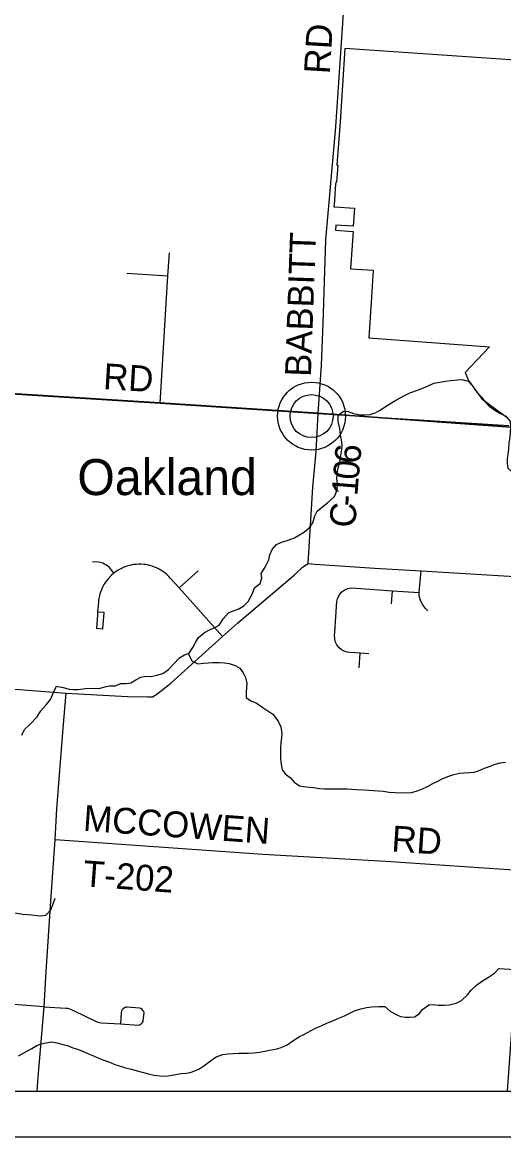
# Model space of a CAD drawing. Extents: x 0 to 91.3, y -0.7 to 22.
# Drawn here: x 3.464 to 4.519, y 14 to 16.443 of the extents above; entities that cross this region are included whole.
import ezdxf

# ---------------------------------------------------------------- set-up
doc = ezdxf.new("R2010")
doc.units = 0
for name, color, linetype in [('GM_X_Corporation', 7, 'Continuous'), ('GM_X_County_Road', 7, 'Continuous'), ('GM_X_County_Road_Text', 7, 'Continuous'), ('GM_X_Minor_River', 7, 'Continuous'), ('GM_X_Township_Road', 7, 'Continuous'), ('GM_X_Township_Road_Text', 7, 'Continuous'), ('GM_X_Unincorporated', 7, 'Continuous'), ('GM_X_Unincorporated_Location', 7, 'Continuous'), ('GM_X_Unincorporated_Text', 7, 'Continuous'), ('SH_Data', 7, 'Continuous')]:
    doc.layers.add(name, color=color, linetype=linetype)

msp = doc.modelspace()

# ---------------------------------------------------------------- linework, layer by layer
at = {"layer": 'GM_X_Corporation'}
for points in [[(2.1, 20.8844), (2.1, 14.1), (4.5273, 14.1), (4.5361, 14.2234), (4.5616, 14.5843), (4.5901, 15.0403), (4.6027, 15.2253), (4.6241, 15.5494), (4.624, 15.5538), (4.6966, 16.7952), (4.7039, 16.921), (4.7369, 17.4842), (4.7381, 17.5094), (4.7391, 17.5254), (4.7562, 17.8002), (4.7688, 17.9561), (4.7799, 18.0944), (4.7833, 18.1361), (4.8242, 18.6326)], [(2.1, 20.8844), (2.1, 15.7138), (2.3611, 15.6969), (2.7426, 15.6727), (3.1007, 15.6507), (3.7652, 15.6088), (4.1118, 15.5861), (4.6241, 15.5494), (4.624, 15.5538), (4.6966, 16.7952), (4.7039, 16.921), (4.7369, 17.4842), (4.7381, 17.5094), (4.7391, 17.5254), (4.7562, 17.8002), (4.7688, 17.9561), (4.7799, 18.0944), (4.7833, 18.1361), (4.8242, 18.6326)], [(4.5546, 16.3598), (4.1706, 16.3862), (4.16, 16.225), (4.1532, 16.1304), (4.1551, 16.1302), (4.1524, 16.0927), (4.1505, 16.0926), (4.1496, 16.0795), (4.1486, 16.0657), (4.1476, 16.0522), (4.1467, 16.0387), (4.1482, 16.0387), (4.1915, 16.036), (4.19, 16.0161), (4.1884, 15.9961), (4.1509, 15.9985), (4.1502, 15.9873), (4.189, 15.9846), (4.1876, 15.9653), (4.1831, 15.903), (4.2328, 15.8999), (4.2283, 15.8297), (4.2234, 15.7519), (4.4873, 15.7321), (4.434, 15.6753), (4.4414, 15.6583), (4.4708, 15.6178), (4.5262, 15.577)]]:
    msp.add_lwpolyline(points, dxfattribs=at)
msp.add_lwpolyline([(2.1, 15.7138), (2.1, 14.1), (4.5273, 14.1), (4.5361, 14.2234), (4.5616, 14.5843), (4.5901, 15.0403), (4.6027, 15.2253), (4.6241, 15.5494), (4.1118, 15.5861), (3.7652, 15.6088), (3.1007, 15.6507), (2.7426, 15.6727), (2.3611, 15.6969)], close=True, dxfattribs=at)
at = {"layer": 'GM_X_County_Road'}
msp.add_line((4.112, 15.5855), (4.5298, 15.5592), dxfattribs=at)
for points in [[(4.112, 15.5855), (4.1196, 15.6918), (4.1232, 15.7838), (4.1286, 15.9666), (4.1509, 16.2143), (4.1988, 16.9297), (4.2129, 17.1593), (4.2202, 17.2471)], [(2.7944, 15.669), (3.1009, 15.6502), (3.7654, 15.6083), (4.112, 15.5855)], [(4.0898, 15.2565), (4.1003, 15.4241), (4.1076, 15.5024), (4.112, 15.5855)], [(3.9024, 15.0967), (3.9353, 15.1263), (4.0599, 15.2323), (4.0777, 15.2484), (4.0898, 15.2565)], [(4.0898, 15.2565), (4.1044, 15.2553), (4.2363, 15.2464), (4.3377, 15.2405), (4.603, 15.2248)], [(3.5594, 14.9727), (3.6939, 14.9655), (3.7377, 14.9648), (3.7487, 14.9646), (3.7581, 14.97), (3.7893, 14.9946), (3.9024, 15.0967)], [(2.5387, 15.0425), (2.6121, 15.0373), (2.706, 15.0307), (2.8364, 15.0213), (2.8571, 15.0199), (2.971, 15.012), (3.0369, 15.0072), (3.0952, 15.0032), (3.3423, 14.9878), (3.4576, 14.9802), (3.5594, 14.9727)], [(3.4961, 14.1), (3.4984, 14.1303), (3.5113, 14.2849), (3.5159, 14.3624), (3.5261, 14.5167), (3.5357, 14.6514), (3.5391, 14.7192), (3.553, 14.8961), (3.5594, 14.9727)]]:
    msp.add_lwpolyline(points, dxfattribs=at)
at = {"layer": 'GM_X_Minor_River'}
for points in [[(3.5761, 14.9807), (3.586, 14.9806), (3.6019, 14.9824), (3.6179, 14.9834), (3.6319, 14.983), (3.6441, 14.9863), (3.6547, 14.9885), (3.6676, 14.9888), (3.679, 14.9937), (3.6912, 14.9936), (3.7014, 14.9955), (3.7121, 15.0019), (3.7235, 15.0079), (3.7353, 15.0097), (3.7459, 15.0092), (3.7585, 15.0122), (3.7718, 15.0159), (3.784, 15.0246), (3.795, 15.0363), (3.8084, 15.0499), (3.8191, 15.0562), (3.8294, 15.0604), (3.8374, 15.0728), (3.8428, 15.0834), (3.8501, 15.0944), (3.863, 15.1057), (3.8756, 15.1121), (3.8855, 15.1162), (3.895, 15.1218), (3.9046, 15.1362), (3.9157, 15.1487), (3.9282, 15.1535), (3.9385, 15.1572), (3.9488, 15.164), (3.9587, 15.1738), (3.9672, 15.1897), (3.9726, 15.2033), (3.9848, 15.2128), (3.9883, 15.2256), (3.9868, 15.2351), (3.9956, 15.2491), (4.0037, 15.265), (4.0064, 15.2756), (4.0114, 15.2874), (4.021, 15.2987), (4.0316, 15.3036), (4.0442, 15.3073), (4.0602, 15.3133), (4.0708, 15.3197), (4.0819, 15.326), (4.093, 15.3358), (4.1006, 15.346), (4.1045, 15.3612), (4.1099, 15.3718), (4.1232, 15.3827), (4.1328, 15.3899), (4.1476, 15.4038), (4.1534, 15.4182), (4.1543, 15.4323), (4.1528, 15.4421), (4.154, 15.4516), (4.1552, 15.4634), (4.1599, 15.4831), (4.1619, 15.4933), (4.1639, 15.5066), (4.1643, 15.5172), (4.1632, 15.5279), (4.161, 15.5385), (4.1592, 15.5529), (4.1559, 15.5681), (4.156, 15.5822), (4.1678, 15.5908), (4.178, 15.59), (4.1898, 15.5858), (4.2038, 15.583), (4.2152, 15.5826), (4.2262, 15.5836), (4.2368, 15.5874), (4.2467, 15.5923), (4.2631, 15.6035), (4.2799, 15.6137), (4.2917, 15.6201), (4.3012, 15.6253), (4.3115, 15.6302), (4.3256, 15.6351), (4.3358, 15.6392), (4.3514, 15.6455), (4.3659, 15.6519), (4.3784, 15.6545), (4.3914, 15.6563), (4.4035, 15.6577), (4.4172, 15.6592), (4.4267, 15.6603), (4.4407, 15.6564), (4.4494, 15.6468), (4.4584, 15.635), (4.4697, 15.6213), (4.478, 15.6114), (4.4867, 15.6018), (4.4991, 15.593), (4.5101, 15.5865)], [(4.5101, 15.5865), (4.5233, 15.5796), (4.5328, 15.5678), (4.5338, 15.5564), (4.5326, 15.5431), (4.5318, 15.5336), (4.5302, 15.5211), (4.529, 15.5078), (4.5274, 15.4965), (4.5266, 15.4866), (4.5265, 15.4767), (4.5276, 15.4661), (4.54, 15.455), (4.5517, 15.4462), (4.5638, 15.437), (4.5778, 15.4278), (4.6085, 15.4127)], [(3.8273, 15.0595), (3.8357, 15.0429), (3.8486, 15.0371), (3.8607, 15.0382), (3.871, 15.0392), (3.8808, 15.0396), (3.8941, 15.0395), (3.907, 15.039), (3.9173, 15.0378), (3.9298, 15.0328), (3.94, 15.0274), (3.9479, 15.0168), (3.9524, 15.0069), (3.9557, 14.9947), (3.9553, 14.9848), (3.9544, 14.975), (3.9544, 14.9632), (3.9642, 14.956), (3.9763, 14.9513), (3.9884, 14.9425), (3.9997, 14.9352), (4.0126, 14.9268), (4.0246, 14.9112), (4.0303, 14.8986), (4.0321, 14.8846), (4.0316, 14.8743), (4.03, 14.8645), (4.0296, 14.8527), (4.0294, 14.8299), (4.0309, 14.8163), (4.0331, 14.8053), (4.0399, 14.7957), (4.0512, 14.7866), (4.0591, 14.777), (4.0712, 14.769), (4.0807, 14.7682), (4.0924, 14.7666), (4.1019, 14.7654), (4.1148, 14.7634), (4.1258, 14.7626), (4.1383, 14.7625), (4.1501, 14.7628), (4.1759, 14.7627), (4.1861, 14.7618), (4.196, 14.7614), (4.2116, 14.7602), (4.2233, 14.7597), (4.2336, 14.7589), (4.2446, 14.7585), (4.2548, 14.7576), (4.2677, 14.7557), (4.281, 14.7544), (4.306, 14.7543), (4.3163, 14.755), (4.3269, 14.7576), (4.3395, 14.7617), (4.3517, 14.7681), (4.3631, 14.7741), (4.3741, 14.7797), (4.3855, 14.7853), (4.3985, 14.7902), (4.4095, 14.7939), (4.4217, 14.7969), (4.4312, 14.798), (4.4441, 14.7986), (4.4536, 14.7993), (4.4635, 14.8023), (4.4768, 14.8079), (4.4878, 14.812), (4.4977, 14.8158), (4.511, 14.8195), (4.5224, 14.8213)], [(3.4624, 14.8804), (3.4681, 14.8925), (3.4811, 14.9046), (3.4964, 14.9204), (3.5044, 14.9336), (3.5159, 14.9469), (3.5255, 14.9589), (3.532, 14.9741), (3.5382, 14.9881), (3.553, 14.9846), (3.5666, 14.9811), (3.5761, 14.9807)], [(3.447, 14.4907), (3.4645, 14.488), (3.474, 14.4871), (3.4846, 14.4863), (3.4956, 14.4851), (3.5058, 14.4843), (3.5153, 14.4854), (3.526, 14.4975), (3.531, 14.5103), (3.5353, 14.5228)], [(3.8339, 14.1412), (3.8502, 14.1479), (3.8613, 14.1551), (3.8762, 14.1667), (3.8887, 14.1754), (3.9028, 14.1802), (3.9138, 14.1817), (3.926, 14.1824), (3.9385, 14.1831), (3.948, 14.183), (3.9586, 14.1833), (3.9719, 14.184), (3.9833, 14.1851), (3.9951, 14.1873), (4.0057, 14.1895), (4.0213, 14.1928), (4.0312, 14.1954), (4.0441, 14.2014), (4.0567, 14.2101), (4.0712, 14.2198), (4.0807, 14.2243), (4.0967, 14.233), (4.1074, 14.2386), (4.1184, 14.2431), (4.1325, 14.2495), (4.1443, 14.2543), (4.1549, 14.2592), (4.1694, 14.2652), (4.1812, 14.2712), (4.1915, 14.2761), (4.2059, 14.2805), (4.2181, 14.2835), (4.2299, 14.2846), (4.2443, 14.2856), (4.2579, 14.2852), (4.2708, 14.2748), (4.2829, 14.2679), (4.2927, 14.2637), (4.3037, 14.2621), (4.3136, 14.2621), (4.3235, 14.2628), (4.3337, 14.2691), (4.341, 14.279), (4.3547, 14.2891), (4.365, 14.2898), (4.376, 14.2886), (4.3893, 14.2882), (4.3991, 14.2889), (4.4147, 14.2926), (4.4265, 14.2986), (4.4391, 14.311), (4.4472, 14.3212), (4.459, 14.3322), (4.4701, 14.3401), (4.4857, 14.3495), (4.4986, 14.3585), (4.5082, 14.3691), (4.5434, 14.3663)], [(3.4549, 14.1772), (3.4645, 14.1825), (3.4751, 14.1885), (3.4846, 14.1937), (3.4953, 14.1997), (3.5048, 14.2035), (3.5151, 14.2057), (3.528, 14.2079), (3.5432, 14.2051), (3.5526, 14.2024), (3.5625, 14.1997), (3.5746, 14.1951), (3.5845, 14.192), (3.5977, 14.1866), (3.6087, 14.182), (3.6193, 14.177), (3.6291, 14.1728), (3.642, 14.1681), (3.6534, 14.1639), (3.6666, 14.1581), (3.6764, 14.1554), (3.6897, 14.1511), (3.7026, 14.148), (3.7155, 14.1442), (3.7261, 14.1418), (3.7405, 14.1379), (3.7518, 14.1348), (3.7659, 14.1332), (3.7765, 14.1328), (3.7879, 14.1342), (3.8004, 14.1364), (3.8111, 14.1383), (3.8232, 14.139), (3.8339, 14.1412)]]:
    msp.add_lwpolyline(points, dxfattribs=at)
at = {"layer": 'GM_X_Township_Road'}
for p, q in [((3.693, 15.8935), (3.7825, 15.8872)), ((3.807, 15.2031), (3.8491, 15.2404)), ((4.2731, 15.1686), (4.2747, 15.1971)), ((4.2019, 15.0281), (4.2041, 15.0599))]:
    msp.add_line(p, q, dxfattribs=at)
for points in [[(3.7654, 15.6083), (3.7825, 15.8872), (3.7859, 15.9376)], [(3.6643, 15.2356), (3.6605, 15.2405), (3.6566, 15.2453), (3.6545, 15.2477), (3.6513, 15.2507), (3.6481, 15.253), (3.6437, 15.2556), (3.6397, 15.2573), (3.6353, 15.2587), (3.6303, 15.2594), (3.6173, 15.2603)], [(3.9024, 15.0967), (3.807, 15.2031), (3.7878, 15.2249), (3.7849, 15.2283), (3.7806, 15.2324), (3.7751, 15.2369), (3.7712, 15.2396), (3.7671, 15.242), (3.7632, 15.2444), (3.7577, 15.2472), (3.7531, 15.2491), (3.7482, 15.2509), (3.7425, 15.2525), (3.7379, 15.2536), (3.7338, 15.2543), (3.7304, 15.2547), (3.7237, 15.2552), (3.7183, 15.2552), (3.713, 15.2548), (3.7072, 15.2543), (3.6989, 15.2525), (3.693, 15.2507), (3.6864, 15.2486), (3.6792, 15.2454), (3.6738, 15.2423), (3.6693, 15.2395), (3.6643, 15.2356), (3.6582, 15.2306), (3.6523, 15.224), (3.6473, 15.2178), (3.6446, 15.2138), (3.6426, 15.2106), (3.6402, 15.2064), (3.6376, 15.2009), (3.6356, 15.1954), (3.6337, 15.19), (3.6321, 15.1828), (3.6309, 15.177), (3.6303, 15.1719), (3.6287, 15.1505), (3.6282, 15.1433)], [(4.3527, 15.1533), (4.3464, 15.1587), (4.3414, 15.1661), (4.3376, 15.173), (4.3351, 15.18), (4.3336, 15.1875), (4.3332, 15.1929), (4.3377, 15.2405)], [(4.2228, 15.0589), (4.2041, 15.0599), (4.1816, 15.0618), (4.1754, 15.0624), (4.1688, 15.0643), (4.1634, 15.0673), (4.1571, 15.0724), (4.1527, 15.0785), (4.1494, 15.0856), (4.1482, 15.0923), (4.1481, 15.099), (4.1487, 15.1059), (4.1533, 15.1738), (4.1542, 15.1791), (4.1563, 15.1847), (4.1594, 15.1893), (4.1637, 15.1947), (4.1704, 15.1993), (4.1769, 15.2021), (4.1844, 15.2033), (4.1955, 15.2025), (4.2747, 15.1971), (4.3332, 15.1929)], [(3.6282, 15.1433), (3.626, 15.1147), (3.6404, 15.1134), (3.6431, 15.1493), (3.6298, 15.1501)], [(3.5357, 14.6514), (3.9905, 14.6197), (4.2607, 14.6038), (4.5619, 14.5838)], [(3.5113, 14.2849), (3.425, 14.2913)], [(3.5113, 14.2849), (3.5586, 14.2818), (3.5623, 14.2816), (3.5674, 14.2803), (3.5722, 14.2783), (3.5772, 14.2761), (3.6238, 14.2535), (3.6263, 14.2523), (3.6294, 14.2514), (3.6324, 14.2505), (3.6364, 14.2499), (3.6787, 14.2473), (3.7175, 14.2445), (3.7204, 14.2454), (3.7226, 14.2468), (3.7248, 14.2482), (3.7267, 14.2506), (3.7284, 14.2528), (3.7288, 14.2551), (3.7303, 14.2719), (3.7296, 14.2745), (3.728, 14.2768), (3.7261, 14.2789), (3.7237, 14.2808), (3.7205, 14.2822), (3.6933, 14.2841), (3.6906, 14.2837), (3.6878, 14.2825), (3.6848, 14.2806), (3.6826, 14.2784), (3.6807, 14.2753), (3.68, 14.2723), (3.6787, 14.2473)]]:
    msp.add_lwpolyline(points, dxfattribs=at)
at = {"layer": 'GM_X_Unincorporated'}
for radius in [0.0744, 0.0472]:
    msp.add_circle((4.0975, 15.5799), radius, dxfattribs=at)
at = {"layer": 'GM_X_Unincorporated_Location'}
msp.add_line((4.0975, 15.5799), (4.0975, 15.5799), dxfattribs=at)
at = {"layer": 'SH_Data'}
for p, q in [((2.1, 14.1), (8.9, 14.1)), ((2, 14), (9, 14))]:
    msp.add_line(p, q, dxfattribs=at)

# ---------------------------------------------------------------- texts
at = {"layer": 'GM_X_County_Road_Text'}
for s, height, rotation, p in [('RD', 0.05682, 86.5466, (4.1376, 16.329)), ('BABBITT', 0.05682, 87.9489, (4.096, 15.6656)), ('RD', 0.05682, 356.5467, (3.6398, 15.6392)), ('6', 0.0568, 85.3635, (4.204, 15.4743)), ('0', 0.0568, 84.5695, (4.2006, 15.4386)), ('1', 0.0568, 85.5462, (4.1979, 15.404)), ('-', 0.0568, 86.2503, (4.1964, 15.3809)), ('C', 0.0568, 86.5595, (4.1936, 15.3344))]:
    msp.add_text(s, height=height, rotation=rotation, dxfattribs=at).set_placement(p)
at = {"layer": 'GM_X_Township_Road_Text'}
for s, rotation, p in [('MCCOWEN', 355.9146, (3.5958, 14.6709)), ('RD', 356.0531, (4.2716, 14.6258)), ('T-202', 355.7742, (3.5953, 14.5494))]:
    msp.add_text(s, height=0.05682, rotation=rotation, dxfattribs=at).set_placement(p)
at = {"layer": 'GM_X_Unincorporated_Text'}
msp.add_text('Oakland', height=0.07898, rotation=0, dxfattribs=at).set_placement((3.5842, 15.4068))

doc.saveas('drawing.dxf')
